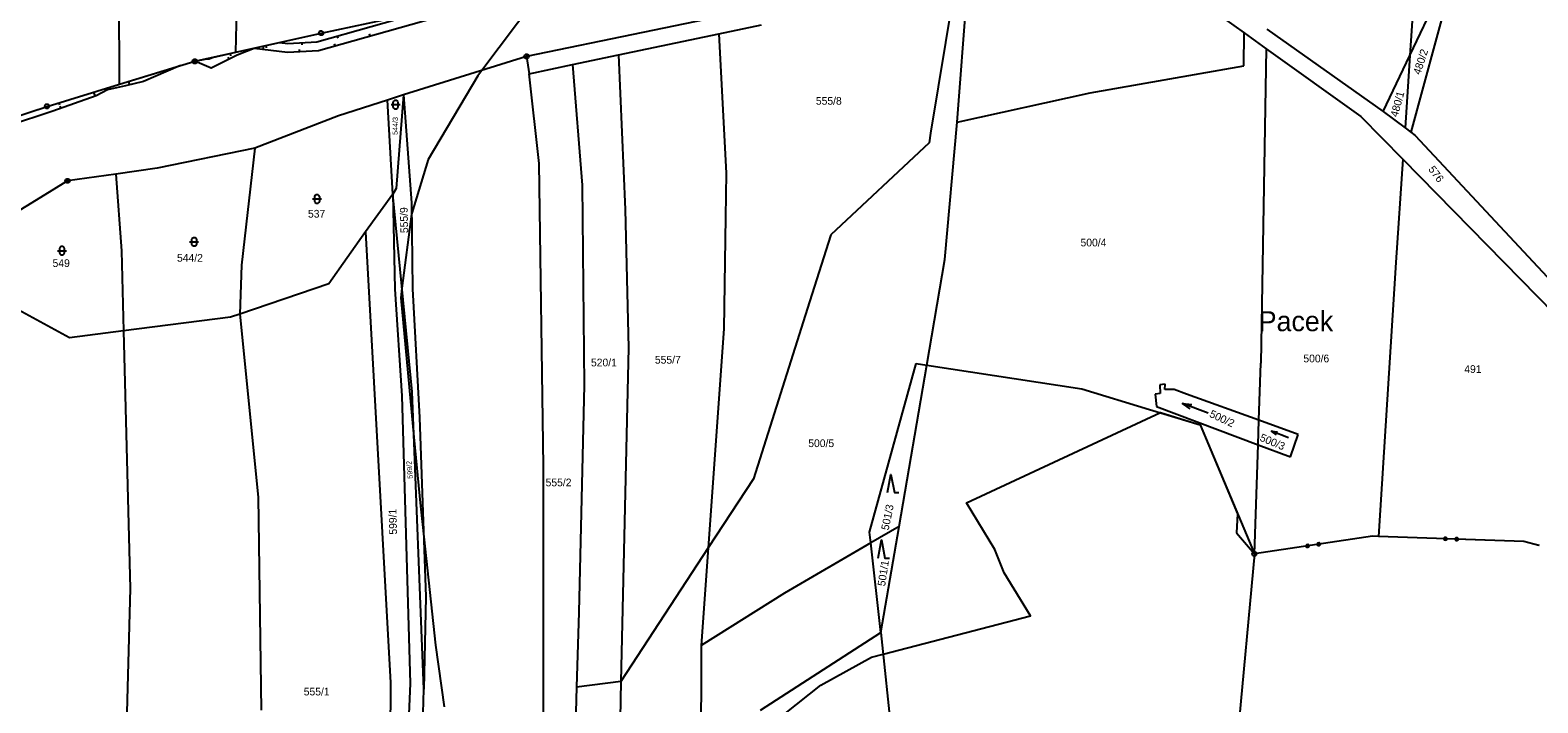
# Model space of a CAD drawing. Extents: x -760978 to -760029, y -1177282 to -1176414.
# Drawn here: x -760612.3 to -760280.9, y -1176773.3 to -1176625.4 of the extents above; entities that cross this region are included whole.
import ezdxf

# ---------------------------------------------------------------- set-up
doc = ezdxf.new("R2010")
doc.units = 0
for name, color, linetype in [('1', 7, 'Continuous'), ('11', 7, 'Continuous'), ('13', 7, 'Continuous'), ('2', 7, 'Continuous'), ('3', 7, 'Continuous'), ('7', 7, 'Continuous'), ('8', 7, 'Continuous')]:
    doc.layers.add(name, color=color, linetype=linetype)

msp = doc.modelspace()

# ---------------------------------------------------------------- linework, layer by layer
at = {"layer": '1'}
for p, q in [((-760306.15, -1176586.7), (-760309.05, -1176630.97)), ((-760592.73, -1176637.28), (-760592.8, -1176597.68)), ((-760567.14, -1176630.22), (-760566.35, -1176599.89)), ((-760376.5, -1176603.8), (-760345.47, -1176625.99)), ((-760408.28, -1176610.61), (-760414.38, -1176648.03)), ((-760408.53, -1176645.64), (-760405.78, -1176609.49)), ((-760309.05, -1176630.97), (-760299.46, -1176610.83)), ((-760300.06, -1176615.64), (-760308.84, -1176647.82)), ((-760452.06, -1176620.62), (-760503.19, -1176631.16)), ((-760548.37, -1176626.03), (-760534.62, -1176623.13)), ((-760460.94, -1176626.16), (-760451.55, -1176624.19)), ((-760340.45, -1176625.18), (-760314.91, -1176643.27)), ((-760567.14, -1176630.22), (-760548.37, -1176626.03)), ((-760483.02, -1176630.81), (-760460.94, -1176626.16)), ((-760460.94, -1176626.16), (-760459.36, -1176656.79)), ((-760345.53, -1176633.23), (-760345.47, -1176625.99)), ((-760345.47, -1176625.99), (-760340.61, -1176629.47)), ((-760576.13, -1176632.22), (-760567.14, -1176630.22)), ((-760503.19, -1176631.16), (-760530.25, -1176639.59)), ((-760503.19, -1176631.16), (-760502.67, -1176634.94)), ((-760493.11, -1176632.93), (-760483.02, -1176630.81)), ((-760483.02, -1176630.81), (-760481.53, -1176664.8)), ((-760340.61, -1176629.47), (-760341.79, -1176698.62)), ((-760340.61, -1176629.47), (-760319.79, -1176644.36)), ((-760314.91, -1176643.27), (-760309.05, -1176630.97)), ((-760309.05, -1176630.97), (-760310.09, -1176646.88)), ((-760592.73, -1176637.28), (-760576.13, -1176632.22)), ((-760502.67, -1176634.94), (-760493.11, -1176632.93)), ((-760500.43, -1176654.71), (-760502.67, -1176634.94)), ((-760493.11, -1176632.93), (-760490.99, -1176659.46)), ((-760379.28, -1176639.17), (-760345.53, -1176633.23)), ((-760608.63, -1176642.13), (-760592.73, -1176637.28)), ((-760533.8, -1176640.74), (-760544.57, -1176644.23)), ((-760530.25, -1176639.59), (-760533.8, -1176640.74)), ((-760532.64, -1176661.45), (-760533.8, -1176640.74)), ((-760530.25, -1176639.59), (-760531.88, -1176660.23)), ((-760530.25, -1176639.59), (-760528.51, -1176663.36)), ((-760408.53, -1176645.64), (-760379.28, -1176639.17)), ((-760623.28, -1176646.96), (-760608.63, -1176642.13)), ((-760544.57, -1176644.23), (-760562.94, -1176651.35)), ((-760319.79, -1176644.36), (-760310.61, -1176653.73)), ((-760314.91, -1176643.27), (-760310.09, -1176646.88)), ((-760414.38, -1176648.03), (-760414.73, -1176650.16)), ((-760411.23, -1176675.79), (-760408.53, -1176645.64)), ((-760310.09, -1176646.88), (-760308.84, -1176647.82)), ((-760308.84, -1176647.82), (-760307.87, -1176648.55)), ((-760562.94, -1176651.35), (-760584.42, -1176655.73)), ((-760562.94, -1176651.35), (-760565.87, -1176677.06)), ((-760414.73, -1176650.16), (-760436.33, -1176670.35)), ((-760307.87, -1176648.55), (-760276.77, -1176681.83)), ((-760499.51, -1176721.27), (-760500.43, -1176654.71)), ((-760310.61, -1176653.73), (-760312.15, -1176676.44)), ((-760310.61, -1176653.73), (-760277.32, -1176687.71)), ((-760593.49, -1176657.01), (-760604.12, -1176658.52)), ((-760584.42, -1176655.73), (-760593.49, -1176657.01)), ((-760593.49, -1176657.01), (-760592.27, -1176673.92)), ((-760459.36, -1176656.79), (-760459.5, -1176666.49)), ((-760604.12, -1176658.52), (-760610.03, -1176662.14)), ((-760532.64, -1176661.45), (-760538.59, -1176669.76)), ((-760531.88, -1176660.23), (-760532.64, -1176661.45)), ((-760532.64, -1176661.45), (-760532.14, -1176682.33)), ((-760528.38, -1176704.92), (-760532.64, -1176661.45)), ((-760490.99, -1176659.46), (-760490.54, -1176703.47)), ((-760610.03, -1176662.14), (-760622.64, -1176669.86)), ((-760528.51, -1176663.36), (-760528.28, -1176682.3)), ((-760481.53, -1176664.8), (-760480.8, -1176695.22)), ((-760459.5, -1176666.49), (-760459.87, -1176691.05)), ((-760538.59, -1176669.76), (-760546.64, -1176681.19)), ((-760538.59, -1176669.76), (-760533.09, -1176768.95)), ((-760436.33, -1176670.35), (-760441.01, -1176685.13)), ((-760592.27, -1176673.92), (-760591.82, -1176691.5)), ((-760565.87, -1176677.06), (-760566.25, -1176687.81)), ((-760415.23, -1176699.08), (-760411.23, -1176675.79)), ((-760312.15, -1176676.44), (-760315.94, -1176736.72)), ((-760546.64, -1176681.19), (-760566.25, -1176687.81)), ((-760603.68, -1176693.02), (-760622.14, -1176683.02)), ((-760532.14, -1176682.33), (-760530.6, -1176705.77)), ((-760528.28, -1176682.3), (-760526.74, -1176710.59)), ((-760566.25, -1176687.81), (-760568.28, -1176688.49)), ((-760566.25, -1176687.81), (-760562.19, -1176728.12)), ((-760441.01, -1176685.13), (-760453.35, -1176724.07)), ((-760591.82, -1176691.5), (-760603.68, -1176693.02)), ((-760568.28, -1176688.49), (-760591.82, -1176691.5)), ((-760591.82, -1176691.5), (-760590.35, -1176748.16)), ((-760459.87, -1176691.05), (-760463.29, -1176739.26)), ((-760480.8, -1176695.22), (-760482.48, -1176768.6)), ((-760427.8, -1176735.75), (-760417.57, -1176698.72)), ((-760421.33, -1176734.52), (-760415.23, -1176699.08)), ((-760417.57, -1176698.72), (-760415.23, -1176699.08)), ((-760415.23, -1176699.08), (-760381.14, -1176704.28)), ((-760342.22, -1176711.16), (-760341.79, -1176698.62)), ((-760490.54, -1176703.47), (-760491.73, -1176753.38)), ((-760381.14, -1176704.28), (-760366.25, -1176708.78)), ((-760362.85, -1176703.2), (-760363.97, -1176703.35)), ((-760363.97, -1176703.35), (-760363.89, -1176705.32)), ((-760362.87, -1176704.39), (-760362.85, -1176703.2)), ((-760360.81, -1176704.43), (-760362.87, -1176704.39)), ((-760358.12, -1176705.4), (-760360.81, -1176704.43)), ((-760530.6, -1176705.77), (-760528.83, -1176769.08)), ((-760525.79, -1176770.28), (-760528.38, -1176704.92)), ((-760363.89, -1176705.32), (-760365.01, -1176705.45)), ((-760365.01, -1176705.45), (-760364.71, -1176708.14)), ((-760342.22, -1176711.16), (-760358.12, -1176705.4)), ((-760526.74, -1176710.59), (-760525.35, -1176750)), ((-760366.25, -1176708.78), (-760355.13, -1176712.14)), ((-760364.71, -1176708.14), (-760342.4, -1176716.54)), ((-760342.4, -1176716.54), (-760342.22, -1176711.16)), ((-760333.59, -1176714.28), (-760342.22, -1176711.16)), ((-760355.13, -1176712.14), (-760343.22, -1176740.55)), ((-760335.28, -1176719.22), (-760333.59, -1176714.28)), ((-760343.22, -1176740.55), (-760342.4, -1176716.54)), ((-760342.4, -1176716.54), (-760335.28, -1176719.22)), ((-760499.51, -1176807.73), (-760499.51, -1176721.27)), ((-760453.35, -1176724.07), (-760463.29, -1176739.26)), ((-760562.19, -1176728.12), (-760561.57, -1176774.94)), ((-760421.33, -1176734.52), (-760427.53, -1176738.14)), ((-760425.3, -1176757.87), (-760421.33, -1176734.52)), ((-760427.53, -1176738.14), (-760427.8, -1176735.75)), ((-760317.26, -1176736.67), (-760343.22, -1176740.55)), ((-760315.94, -1176736.72), (-760317.26, -1176736.67)), ((-760283.97, -1176737.82), (-760315.94, -1176736.72)), ((-760280.52, -1176738.75), (-760283.97, -1176737.82)), ((-760463.29, -1176739.26), (-760482.48, -1176768.6)), ((-760463.29, -1176739.26), (-760464.81, -1176760.74)), ((-760427.53, -1176738.14), (-760446.49, -1176749.19)), ((-760425.3, -1176757.87), (-760427.53, -1176738.14)), ((-760343.22, -1176740.55), (-760351.15, -1176826.4)), ((-760590.35, -1176748.16), (-760591.5, -1176790.17)), ((-760525.35, -1176750), (-760525.79, -1176770.28)), ((-760446.49, -1176749.19), (-760464.81, -1176760.74)), ((-760491.73, -1176753.38), (-760492.21, -1176769.91)), ((-760464.81, -1176760.74), (-760464.83, -1176765.57)), ((-760451.75, -1176774.96), (-760425.3, -1176757.87)), ((-760425.3, -1176757.87), (-760403.29, -1176966.24)), ((-760464.83, -1176765.57), (-760464.97, -1176799.58)), ((-760533.09, -1176768.95), (-760533.53, -1176811.46)), ((-760528.83, -1176769.08), (-760531.06, -1176827.1)), ((-760528.7, -1176872.66), (-760525.79, -1176770.28)), ((-760492.21, -1176769.91), (-760492.85, -1176794.9)), ((-760482.48, -1176768.6), (-760492.21, -1176769.91)), ((-760482.48, -1176768.6), (-760482.77, -1176785.31))]:
    msp.add_line(p, q, dxfattribs=at)
for points in [[(-760301.4, -1176737.54), (-760301.58, -1176737.34), (-760301.57, -1176737.07), (-760301.37, -1176736.89), (-760301.1, -1176736.9), (-760300.92, -1176737.1), (-760300.93, -1176737.37), (-760301.13, -1176737.55), (-760301.4, -1176737.54), (-760301.36, -1176737.5), (-760301.12, -1176737.51), (-760301.04, -1176737.43), (-760301.44, -1176737.42), (-760301.52, -1176737.34), (-760300.96, -1176737.36), (-760300.96, -1176737.28), (-760301.52, -1176737.26), (-760301.51, -1176737.18), (-760300.95, -1176737.2), (-760300.95, -1176737.12), (-760301.51, -1176737.1), (-760301.43, -1176737.02), (-760301.03, -1176737.03), (-760301.1, -1176736.95), (-760301.34, -1176736.94)], [(-760298.9, -1176737.63), (-760299.08, -1176737.43), (-760299.07, -1176737.16), (-760298.87, -1176736.98), (-760298.6, -1176736.99), (-760298.42, -1176737.18), (-760298.43, -1176737.45), (-760298.63, -1176737.64), (-760298.9, -1176737.63), (-760298.89, -1176737.59), (-760298.65, -1176737.6), (-760298.56, -1176737.52), (-760298.96, -1176737.5), (-760299.04, -1176737.42), (-760298.48, -1176737.44), (-760298.48, -1176737.36), (-760299.04, -1176737.34), (-760299.03, -1176737.26), (-760298.47, -1176737.28), (-760298.47, -1176737.2), (-760299.03, -1176737.18), (-760298.95, -1176737.1), (-760298.55, -1176737.12), (-760298.63, -1176737.04), (-760298.87, -1176737.03)], [(-760331.61, -1176739.14), (-760331.82, -1176738.98), (-760331.86, -1176738.71), (-760331.7, -1176738.5), (-760331.44, -1176738.46), (-760331.22, -1176738.61), (-760331.18, -1176738.88), (-760331.34, -1176739.1), (-760331.61, -1176739.14), (-760331.58, -1176739.09), (-760331.35, -1176739.06), (-760331.28, -1176738.97), (-760331.67, -1176739.03), (-760331.77, -1176738.96), (-760331.21, -1176738.88), (-760331.22, -1176738.8), (-760331.78, -1176738.88), (-760331.79, -1176738.8), (-760331.23, -1176738.72), (-760331.25, -1176738.64), (-760331.8, -1176738.72), (-760331.73, -1176738.63), (-760331.34, -1176738.57), (-760331.43, -1176738.5), (-760331.67, -1176738.54)], [(-760329.13, -1176738.77), (-760329.35, -1176738.61), (-760329.39, -1176738.34), (-760329.23, -1176738.13), (-760328.96, -1176738.09), (-760328.75, -1176738.25), (-760328.71, -1176738.51), (-760328.87, -1176738.73), (-760329.13, -1176738.77), (-760329.13, -1176738.73), (-760328.89, -1176738.69), (-760328.83, -1176738.6), (-760329.22, -1176738.66), (-760329.31, -1176738.59), (-760328.76, -1176738.51), (-760328.77, -1176738.43), (-760329.32, -1176738.51), (-760329.34, -1176738.43), (-760328.78, -1176738.35), (-760328.79, -1176738.27), (-760329.35, -1176738.36), (-760329.28, -1176738.26), (-760328.88, -1176738.21), (-760328.98, -1176738.14), (-760329.21, -1176738.17)]]:
    msp.add_lwpolyline(points, dxfattribs=at)
at = {"layer": '11'}
msp.add_line((-760347.17, -1176735.96), (-760343.22, -1176740.55), dxfattribs=at)
for points in [[(-760501.37, -1176618.7), (-760513.07, -1176634.24), (-760513.95, -1176635.41), (-760524.86, -1176653.84), (-760528.45, -1176665.64), (-760528.48, -1176665.84), (-760530.61, -1176682.15), (-760530.88, -1176684.23), (-760527.99, -1176714.86), (-760526.55, -1176730.06), (-760525.81, -1176736.83), (-760523.24, -1176760.62), (-760521.34, -1176774.21)], [(-760451.68, -1176815.55), (-760451.74, -1176779.89), (-760438.52, -1176769.41), (-760427.39, -1176763.26), (-760424.8, -1176762.59), (-760392.44, -1176754.17), (-760398.23, -1176744.75), (-760400.26, -1176739.63), (-760406.46, -1176729.34), (-760363.88, -1176709.5), (-760355.13, -1176712.14), (-760346.91, -1176731.76), (-760347.17, -1176735.96)], [(-760280.68, -1176738.71), (-760283.97, -1176737.82), (-760298.96, -1176737.3), (-760315.94, -1176736.72), (-760317.26, -1176736.67), (-760343.22, -1176740.55)]]:
    msp.add_lwpolyline(points, dxfattribs=at)
at = {"layer": '13'}
for p, q in [((-760552.66, -1176628.11), (-760552.63, -1176628.61)), ((-760545.28, -1176628.87), (-760545.42, -1176628.39)), ((-760544.83, -1176626.67), (-760544.7, -1176627.15)), ((-760537.58, -1176626.69), (-760537.72, -1176626.21)), ((-760568.58, -1176631.73), (-760568.81, -1176631.29)), ((-760568.37, -1176630.49), (-760568.26, -1176630.98)), ((-760561.09, -1176629.61), (-760561.03, -1176629.12)), ((-760560.56, -1176628.75), (-760560.45, -1176629.24)), ((-760553.13, -1176630.13), (-760553.16, -1176629.63)), ((-760582.95, -1176634.74), (-760583.14, -1176634.28)), ((-760583.08, -1176634.34), (-760582.93, -1176634.81)), ((-760590.73, -1176636.67), (-760590.59, -1176637.15)), ((-760590.47, -1176637.36), (-760590.59, -1176636.88)), ((-760606.04, -1176641.34), (-760605.89, -1176641.82)), ((-760598.38, -1176639), (-760598.24, -1176639.48)), ((-760598.01, -1176639.87), (-760598.18, -1176639.4)), ((-760605.54, -1176642.57), (-760605.71, -1176642.1))]:
    msp.add_line(p, q, dxfattribs=at)
msp.add_lwpolyline([(-760523.48, -1176622.7), (-760548.95, -1176629.91), (-760555.78, -1176630.27), (-760563.06, -1176629.37), (-760566.82, -1176630.84), (-760572.54, -1176633.74), (-760576.13, -1176632.22), (-760573.51, -1176631.64), (-760572.96, -1176631.7), (-760572.23, -1176631.35), (-760567.14, -1176630.22), (-760557.49, -1176628.06), (-760555.72, -1176628.27), (-760549.29, -1176627.93), (-760525.45, -1176621.19)], dxfattribs=at)
msp.add_lwpolyline([(-760676.11, -1176657.05), (-760671.86, -1176656.2), (-760652.4, -1176652.98), (-760630.6, -1176649.37), (-760608.63, -1176642.13), (-760592.73, -1176637.28), (-760579.26, -1176633.17), (-760587.45, -1176636.66), (-760591.4, -1176637.58), (-760595.35, -1176638.5), (-760597.84, -1176639.81), (-760607.33, -1176643.21), (-760617.12, -1176646.44), (-760623.53, -1176648.8), (-760631.69, -1176650.82), (-760639.26, -1176652.44), (-760649.65, -1176654.16), (-760663.67, -1176655.6), (-760668.08, -1176657.06), (-760672.02, -1176657.81)], close=True, dxfattribs=at)
at = {"layer": '3'}
for p, q in [((-760353.38, -1176709.58), (-760359.02, -1176707.52)), ((-760335.72, -1176715), (-760339.48, -1176713.56))]:
    msp.add_line(p, q, dxfattribs=at)
for points in [[(-760533, -1176641.75), (-760531.73, -1176641.75), (-760531, -1176641.75)], [(-760550.27, -1176662.49), (-760549, -1176662.49), (-760548.27, -1176662.49)], [(-760606.34, -1176673.87), (-760605.07, -1176673.87), (-760604.34, -1176673.87)], [(-760577.3, -1176671.92), (-760576.03, -1176671.92), (-760575.3, -1176671.92)], [(-760357.31, -1176708.68), (-760359.02, -1176707.52), (-760356.97, -1176707.74)], [(-760338.35, -1176714.35), (-760339.48, -1176713.56), (-760338.1, -1176713.73)], [(-760423.85, -1176727.09), (-760423.1, -1176723.09), (-760422.35, -1176727.09), (-760421.35, -1176727.09)], [(-760425.92, -1176741.5), (-760425.17, -1176737.5), (-760424.42, -1176741.5), (-760423.42, -1176741.5)]]:
    msp.add_lwpolyline(points, dxfattribs=at)
for points in [[(-760532.5, -1176641.25), (-760532.4, -1176640.96), (-760532.15, -1176640.78), (-760531.84, -1176640.78), (-760531.59, -1176640.96), (-760531.49, -1176641.25), (-760531.49, -1176642.25), (-760531.59, -1176642.54), (-760531.84, -1176642.72), (-760532.15, -1176642.72), (-760532.4, -1176642.54), (-760532.5, -1176642.25)], [(-760549.77, -1176661.99), (-760549.67, -1176661.7), (-760549.42, -1176661.52), (-760549.11, -1176661.52), (-760548.86, -1176661.7), (-760548.76, -1176661.99), (-760548.76, -1176662.99), (-760548.86, -1176663.28), (-760549.11, -1176663.46), (-760549.42, -1176663.46), (-760549.67, -1176663.28), (-760549.77, -1176662.99)], [(-760576.8, -1176671.42), (-760576.7, -1176671.13), (-760576.45, -1176670.95), (-760576.14, -1176670.95), (-760575.89, -1176671.13), (-760575.79, -1176671.42), (-760575.79, -1176672.42), (-760575.89, -1176672.71), (-760576.14, -1176672.89), (-760576.45, -1176672.89), (-760576.7, -1176672.71), (-760576.8, -1176672.42)], [(-760605.84, -1176673.37), (-760605.74, -1176673.08), (-760605.49, -1176672.9), (-760605.18, -1176672.9), (-760604.93, -1176673.08), (-760604.83, -1176673.37), (-760604.83, -1176674.37), (-760604.93, -1176674.66), (-760605.18, -1176674.84), (-760605.49, -1176674.84), (-760605.74, -1176674.66), (-760605.84, -1176674.37)]]:
    msp.add_lwpolyline(points, close=True, dxfattribs=at)
at = {"layer": '8'}
for p, q in [((-760548.49, -1176626.03), (-760548.25, -1176626.03)), ((-760503.31, -1176631.16), (-760503.07, -1176631.16)), ((-760576.25, -1176632.22), (-760576.01, -1176632.22)), ((-760608.75, -1176642.13), (-760608.51, -1176642.13)), ((-760604.24, -1176658.52), (-760604, -1176658.52)), ((-760343.34, -1176740.55), (-760343.1, -1176740.55))]:
    msp.add_line(p, q, dxfattribs=at)
for points in [[(-760548.22, -1176625.55), (-760547.97, -1176625.73), (-760547.87, -1176626.02), (-760547.97, -1176626.31), (-760548.22, -1176626.49), (-760548.53, -1176626.49), (-760548.78, -1176626.31), (-760548.88, -1176626.02), (-760548.78, -1176625.73), (-760548.53, -1176625.55)], [(-760575.98, -1176631.74), (-760575.73, -1176631.92), (-760575.63, -1176632.21), (-760575.73, -1176632.5), (-760575.98, -1176632.68), (-760576.29, -1176632.68), (-760576.54, -1176632.5), (-760576.64, -1176632.21), (-760576.54, -1176631.92), (-760576.29, -1176631.74)], [(-760503.04, -1176630.68), (-760502.79, -1176630.86), (-760502.69, -1176631.15), (-760502.79, -1176631.44), (-760503.04, -1176631.62), (-760503.35, -1176631.62), (-760503.6, -1176631.44), (-760503.7, -1176631.15), (-760503.6, -1176630.86), (-760503.35, -1176630.68)], [(-760608.48, -1176641.65), (-760608.23, -1176641.83), (-760608.13, -1176642.12), (-760608.23, -1176642.41), (-760608.48, -1176642.59), (-760608.79, -1176642.59), (-760609.04, -1176642.41), (-760609.14, -1176642.12), (-760609.04, -1176641.83), (-760608.79, -1176641.65)], [(-760603.97, -1176658.04), (-760603.72, -1176658.22), (-760603.62, -1176658.51), (-760603.72, -1176658.8), (-760603.97, -1176658.98), (-760604.28, -1176658.98), (-760604.53, -1176658.8), (-760604.63, -1176658.51), (-760604.53, -1176658.22), (-760604.28, -1176658.04)], [(-760343.07, -1176740.07), (-760342.82, -1176740.25), (-760342.72, -1176740.54), (-760342.82, -1176740.83), (-760343.07, -1176741.01), (-760343.38, -1176741.01), (-760343.63, -1176740.83), (-760343.73, -1176740.54), (-760343.63, -1176740.25), (-760343.38, -1176740.07)]]:
    msp.add_lwpolyline(points, close=True, dxfattribs=at)

# ---------------------------------------------------------------- texts
at = {"layer": '2'}
for s, height, rotation, p in [('480/2', 1.7, 72.1927, (-760306.73, -1176635.29)), ('480/1', 1.7, 74.5991, (-760311.72, -1176644.59)), ('544/3', 1.14, 89.3814, (-760531.54, -1176648.42)), ('576', 1.7, 307.1054, (-760305.07, -1176656.01)), ('555/9', 1.7, 91.3868, (-760529.22, -1176669.99)), ('500/2', 1.7, 335.0084, (-760353.25, -1176710.36)), ('500/3', 1.7, 337.243, (-760342.17, -1176715.61)), ('599/2', 1.14, 94.7672, (-760528.2, -1176723.98)), ('599/1', 1.7, 91.5587, (-760531.68, -1176736.3)), ('501/3', 1.7, 78.4379, (-760423.62, -1176735.46)), ('501/1', 1.7, 81.4746, (-760424.39, -1176747.75))]:
    msp.add_text(s, height=height, rotation=rotation, dxfattribs=at).set_placement(p)
for s, p in [('555/8', (-760439.61, -1176641.77)), ('537', (-760551.26, -1176666.6)), ('500/4', (-760381.43, -1176672.93)), ('544/2', (-760580.05, -1176676.3)), ('549', (-760607.41, -1176677.46)), ('520/1', (-760489.05, -1176699.32)), ('555/7', (-760475, -1176698.72)), ('500/6', (-760332.44, -1176698.43)), ('491', (-760297.07, -1176700.76)), ('500/5', (-760441.28, -1176717.07)), ('555/2', (-760499.02, -1176725.7)), ('555/1', (-760552.19, -1176771.69))]:
    msp.add_text(s, height=1.7, dxfattribs=at).set_placement(p)
at = {"layer": '7'}
msp.add_text('Pacek', height=4.4, dxfattribs=at).set_placement((-760342.25, -1176691.58))

doc.saveas('drawing.dxf')
